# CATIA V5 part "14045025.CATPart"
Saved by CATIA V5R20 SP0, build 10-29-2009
Part number: 14045025
Definition: NONE
Nomenclature: 14045025
Source: Unknown
Description: 14045025
Bounding box of the stored display mesh (mm): x -12.5 to 50, y -36.5 to 26.406, z -26.6 to 26.6
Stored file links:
  C:\Users\Utente\Desktop\IO LAVORO\3D X SITO CF\X SITO\PLASTICA\RF2\14045025.CATPart
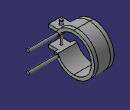
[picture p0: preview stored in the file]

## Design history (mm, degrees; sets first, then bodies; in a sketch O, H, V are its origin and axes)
Body1 "14045025" (main body)
  Solid1: solid without history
